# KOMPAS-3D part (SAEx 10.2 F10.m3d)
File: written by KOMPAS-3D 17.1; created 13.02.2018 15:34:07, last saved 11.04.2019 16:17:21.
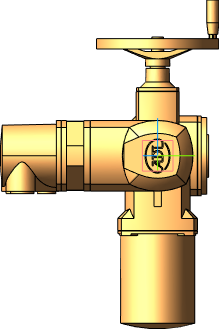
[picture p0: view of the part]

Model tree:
1. Операция без истории:3  (labels: Сталь 20  ГОСТ 1050-2013)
